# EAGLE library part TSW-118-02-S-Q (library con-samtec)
THROUGH-HOLE .025" SQ POST HEADER Source: Samtec TSW.pdf
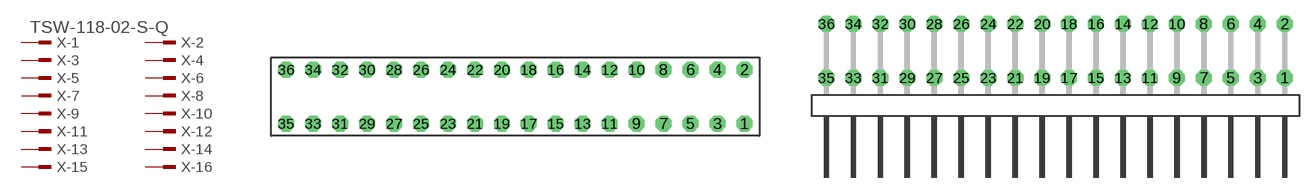
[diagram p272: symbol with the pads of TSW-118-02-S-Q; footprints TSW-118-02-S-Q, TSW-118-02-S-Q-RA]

Designator prefix X; gates -1=MPINV -2=MPIN -3=MPIN -4=MPIN -5=MPIN -6=MPIN -7=MPIN -8=MPIN -9=MPIN -10=MPIN -11=MPIN -12=MPIN -13=MPIN -14=MPIN -15=MPIN -16=MPIN -17=MPIN -18=MPIN -19=MPIN -20=MPIN -21=MPIN -22=MPIN -23=MPIN -24=MPIN -25=MPIN -26=MPIN -27=MPIN -28=MPIN -29=MPIN -30=MPIN -31=MPIN -32=MPIN -33=MPIN -34=MPIN -35=MPIN -36=MPIN

## TSW-118-02-S-Q (OC_FARNELL: unknown; OC_NEWARK: unknown)  [TSW-118-02-S-Q]
1  -1:1  pas
2  -2:1  pas
3  -3:1  pas
4  -4:1  pas
5  -5:1  pas
6  -6:1  pas
7  -7:1  pas
8  -8:1  pas
9  -9:1  pas
10  -10:1  pas
11  -11:1  pas
12  -12:1  pas
13  -13:1  pas
14  -14:1  pas
15  -15:1  pas
16  -16:1  pas
17  -17:1  pas
18  -18:1  pas
19  -19:1  pas
20  -20:1  pas
21  -21:1  pas
22  -22:1  pas
23  -23:1  pas
24  -24:1  pas
25  -25:1  pas
26  -26:1  pas
27  -27:1  pas
28  -28:1  pas
29  -29:1  pas
30  -30:1  pas
31  -31:1  pas
32  -32:1  pas
33  -33:1  pas
34  -34:1  pas
35  -35:1  pas
36  -36:1  pas

## TSW-118-02-S-Q-RA (OC_FARNELL: unknown; OC_NEWARK: unknown)  [TSW-118-02-S-Q-RA]
Pads as for TSW-118-02-S-Q

## Footprint TSW-118-02-S-Q (pad centres in mm)
THROUGH-HOLE .025" SQ POST HEADER Source: Samtec TSW.pdf
drill 1 pad 1.5 octagon: 1 21.59,-2.54; 2 21.59,2.54; 3 19.05,-2.54; 4 19.05,2.54; 5 16.51,-2.54; 6 16.51,2.54; 7 13.97,-2.54; 8 13.97,2.54; 9 11.43,-2.54; 10 11.43,2.54; 11 8.89,-2.54; 12 8.89,2.54; 13 6.35,-2.54; 14 6.35,2.54; 15 3.81,-2.54; 16 3.81,2.54; 17 1.27,-2.54; 18 1.27,2.54; 19 -1.27,-2.54; 20 -1.27,2.54; 21 -3.81,-2.54; 22 -3.81,2.54; 23 -6.35,-2.54; 24 -6.35,2.54; 25 -8.89,-2.54; 26 -8.89,2.54; 27 -11.43,-2.54; 28 -11.43,2.54; 29 -13.97,-2.54; 30 -13.97,2.54; 31 -16.51,-2.54; 32 -16.51,2.54; 33 -19.05,-2.54; 34 -19.05,2.54; 35 -21.59,-2.54; 36 -21.59,2.54

## Footprint TSW-118-02-S-Q-RA (pad centres in mm)
THROUGH-HOLE .025" SQ POST HEADER Source: Samtec TSW.pdf
drill 1 pad 1.5 octagon: 1 21.59,1.524; 2 21.59,6.604; 3 19.05,1.524; 4 19.05,6.604; 5 16.51,1.524; 6 16.51,6.604; 7 13.97,1.524; 8 13.97,6.604; 9 11.43,1.524; 10 11.43,6.604; 11 8.89,1.524; 12 8.89,6.604; 13 6.35,1.524; 14 6.35,6.604; 15 3.81,1.524; 16 3.81,6.604; 17 1.27,1.524; 18 1.27,6.604; 19 -1.27,1.524; 20 -1.27,6.604; 21 -3.81,1.524; 22 -3.81,6.604; 23 -6.35,1.524; 24 -6.35,6.604; 25 -8.89,1.524; 26 -8.89,6.604; 27 -11.43,1.524; 28 -11.43,6.604; 29 -13.97,1.524; 30 -13.97,6.604; 31 -16.51,1.524; 32 -16.51,6.604; 33 -19.05,1.524; 34 -19.05,6.604; 35 -21.59,1.524; 36 -21.59,6.604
